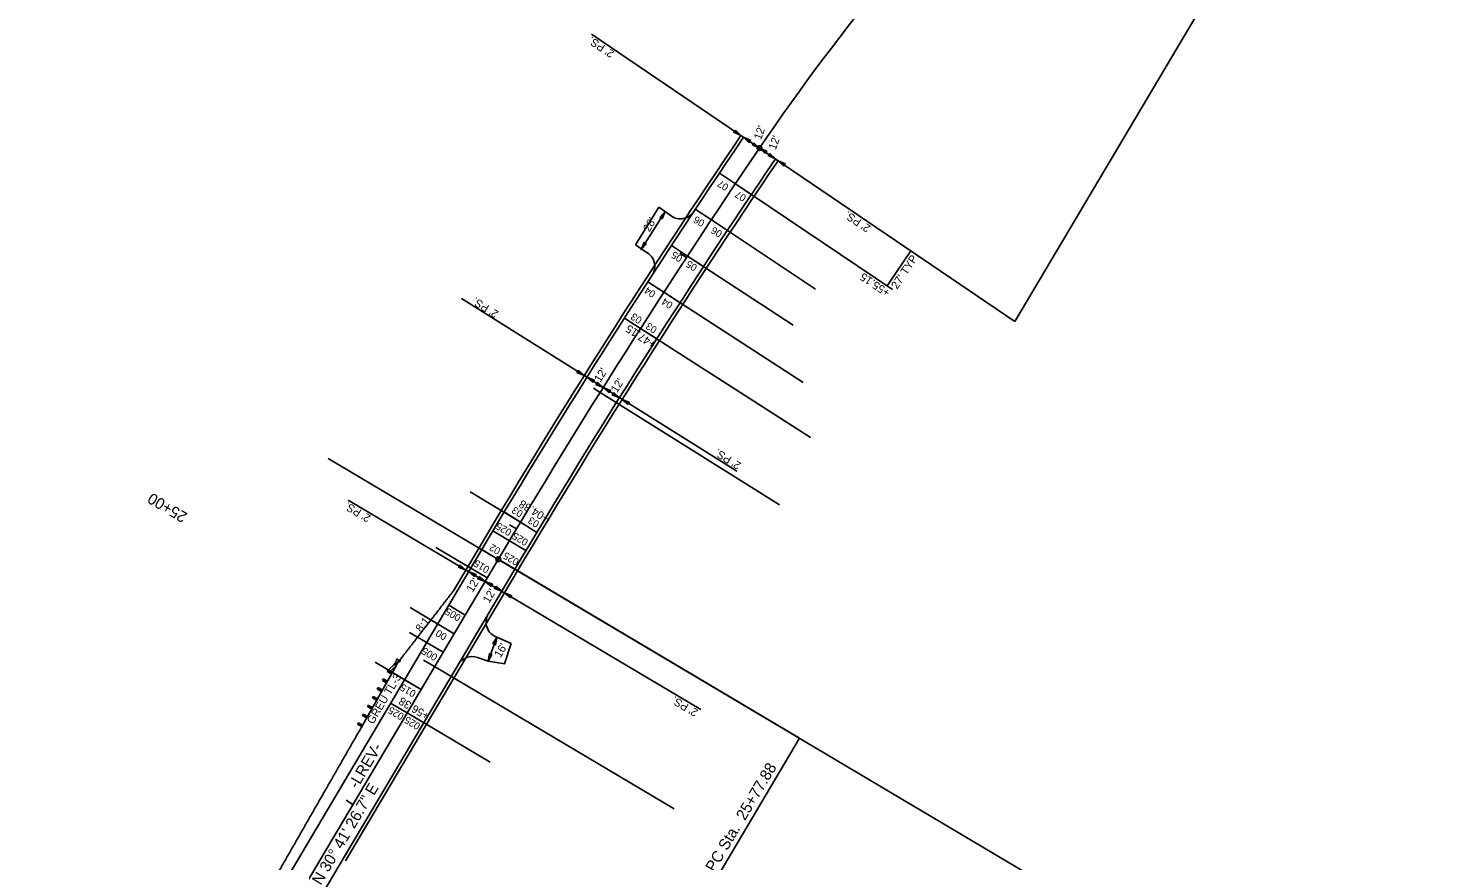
# Model space of a CAD drawing. Extents: x 2138032 to 2141863, y 405316 to 411953.
# Drawn here: x 2140967 to 2141846, y 410524 to 411044 of the extents above; entities that cross this region are included whole.
import ezdxf

# ---------------------------------------------------------------- set-up
doc = ezdxf.new("R2010")
doc.units = 0
for name, color, linetype in [('Prop Dimension', 7, 'Continuous'), ('Prop Dimension Text', 7, 'Continuous'), ('Prop EOT', 7, 'Continuous'), ('Prop Guardrail', 7, 'Continuous'), ('Prop Guardrail Anchor Unit CELL', 7, 'Continuous'), ('Prop Horizontal Alignment', 7, 'Continuous'), ('Prop Horizontal Alignment Direction Label', 7, 'Continuous'), ('Prop Horizontal Alignment Station Label', 7, 'Continuous'), ('Prop Horizontal Alignment Tick Label', 7, 'Continuous'), ('Prop Horizontal Alignment Tick Large', 7, 'Continuous'), ('Prop Horizontal Alignment Tick Small', 7, 'Continuous'), ('Prop Paved Shoulder', 7, 'Continuous'), ('Prop Superelevation  Arrow CELL', 7, 'Continuous'), ('Prop Superelevation Label', 7, 'Continuous'), ('Prop Terminator CELL', 7, 'Continuous'), ('Scratch_Level_5', 7, 'Continuous'), ('Scratch_Level_6', 7, 'Continuous'), ('Scratch_Level_7', 7, 'Continuous')]:
    doc.layers.add(name, color=color, linetype=linetype)

msp = doc.modelspace()

# ---------------------------------------------------------------- linework, layer by layer
at = {"layer": 'Prop Dimension'}
for p, q in [((2141583.48, 410860.49), (2141845.93, 411302.66)), ((2141319.23, 411039.91), (2141583.48, 410860.49)), ((2141507.25, 410880.38), (2141408.99, 410946.33)), ((2141350.17, 410905.39), (2141365.1, 410929.09)), ((2141503.78, 410882.7), (2141518.6, 410904.54)), ((2141409.88, 410766.94), (2141238.04, 410874.86)), ((2141259.95, 410663.36), (2141254.61, 410648.28))]:
    msp.add_line(p, q, dxfattribs=at)
at = {"layer": 'Prop Dimension Text'}
msp.add_line((2141167.11, 410748.94), (2141387.51, 410618.13), dxfattribs=at)
at = {"layer": 'Prop EOT'}
for p, q in [((2141361.18, 410931.91), (2141346.54, 410908.24)), ((2141361.18, 410931.91), (2141368.84, 410926.4)), ((2141346.54, 410908.24), (2141353.27, 410903.78)), ((2140946.62, 410205.9), (2141250.61, 410718.06)), ((2140967.26, 410193.65), (2141271.25, 410705.81)), ((2141268.96, 410659.34), (2141259.95, 410663.36)), ((2141268.96, 410659.34), (2141264.82, 410646.71)), ((2141254.61, 410648.28), (2141247.88, 410650.66)), ((2141264.95, 410646.71), (2141254.61, 410648.28))]:
    msp.add_line(p, q, dxfattribs=at)
for centre, radius, start, end in [((2145560.6, 408159.91), 5012, 145.82249, 149.30926), ((2145560.6, 408159.91), 4988, 145.82249, 149.30926), ((2141374.67, 410934.53), 10, 234.32649, 326.46189), ((2141348.68, 410894.9), 10, 327.00256, 62.64012), ((2141263.28, 410672.79), 10, 149.30926, 250.52331), ((2141244.55, 410641.23), 10, 70.52331, 149.30926)]:
    msp.add_arc(centre, radius, start, end, dxfattribs=at)
at = {"layer": 'Prop Guardrail'}
for points in [[(2141174.38, 410605.3), (2141173.6, 410603.94), (2141173.21, 410603.26), (2141172.83, 410602.58), (2141172.44, 410601.91), (2141172.05, 410601.23), (2141171.66, 410600.55), (2141171.27, 410599.87), (2141170.88, 410599.2), (2141170.49, 410598.52), (2141170.11, 410597.84), (2141169.72, 410597.16), (2141169.33, 410596.48), (2141168.94, 410595.81), (2141168.55, 410595.13), (2141168.16, 410594.45), (2141167.77, 410593.77), (2141167.39, 410593.09), (2141167, 410592.42), (2141166.61, 410591.74), (2141166.22, 410591.06), (2141165.83, 410590.38), (2141165.44, 410589.71), (2141165.05, 410589.03), (2141164.66, 410588.35), (2141164.28, 410587.67), (2141163.89, 410586.99), (2141163.5, 410586.32), (2141163.11, 410585.64), (2141162.72, 410584.96), (2141162.33, 410584.28), (2141161.94, 410583.6), (2141161.56, 410582.93), (2141161.17, 410582.25), (2141160.78, 410581.57), (2141160.39, 410580.89), (2141160, 410580.22), (2141159.61, 410579.54), (2141159.22, 410578.86), (2141158.84, 410578.18), (2141158.45, 410577.5), (2141158.06, 410576.83), (2141157.67, 410576.15), (2141157.28, 410575.47), (2141156.89, 410574.79), (2141156.5, 410574.11), (2141156.12, 410573.44), (2141155.73, 410572.76), (2141155.34, 410572.08), (2141154.95, 410571.4), (2141154.56, 410570.73), (2141154.17, 410570.05), (2141153.78, 410569.37), (2141153.4, 410568.69), (2141153.01, 410568.01), (2141152.62, 410567.34), (2141152.23, 410566.66), (2141151.84, 410565.98), (2141151.45, 410565.3), (2141151.06, 410564.62), (2141150.68, 410563.95), (2141150.29, 410563.27), (2141149.9, 410562.59), (2141149.51, 410561.91), (2141149.12, 410561.24), (2141148.73, 410560.56), (2141148.34, 410559.88), (2141147.96, 410559.2), (2141147.57, 410558.52), (2141147.18, 410557.85), (2141146.79, 410557.17), (2141146.4, 410556.49), (2141146.01, 410555.81), (2141145.62, 410555.13)], [(2141145.62, 410555.13), (2141145.24, 410554.46), (2141144.85, 410553.78), (2141144.46, 410553.1), (2141144.07, 410552.42), (2141143.68, 410551.75), (2141143.29, 410551.07), (2141142.9, 410550.39), (2141142.52, 410549.71), (2141142.13, 410549.03), (2141141.74, 410548.36), (2141141.35, 410547.68), (2141140.96, 410547), (2141140.57, 410546.32), (2141140.18, 410545.64), (2141139.8, 410544.97), (2141139.41, 410544.29), (2141139.02, 410543.61), (2141138.63, 410542.93), (2141138.24, 410542.26), (2141137.85, 410541.58), (2141137.46, 410540.9), (2141137.08, 410540.22), (2141136.69, 410539.54), (2141136.3, 410538.87), (2141135.91, 410538.19), (2141135.52, 410537.51), (2141135.13, 410536.83), (2141134.74, 410536.15), (2141134.36, 410535.48), (2141133.97, 410534.8), (2141133.58, 410534.12), (2141133.19, 410533.44), (2141132.8, 410532.77), (2141132.41, 410532.09), (2141132.02, 410531.41), (2141131.64, 410530.73), (2141131.25, 410530.05), (2141130.86, 410529.38), (2141130.47, 410528.7), (2141130.08, 410528.02), (2141129.69, 410527.34), (2141129.3, 410526.66), (2141128.92, 410525.99), (2141128.53, 410525.31), (2141128.14, 410524.63), (2141127.75, 410523.95), (2141127.36, 410523.28), (2141126.97, 410522.6), (2141126.58, 410521.92), (2141126.2, 410521.24), (2141125.81, 410520.56), (2141125.42, 410519.89), (2141125.03, 410519.21), (2141124.64, 410518.53), (2141124.25, 410517.85), (2141123.86, 410517.17), (2141123.47, 410516.5), (2141123.09, 410515.82), (2141122.7, 410515.14), (2141122.31, 410514.46), (2141121.92, 410513.79), (2141121.53, 410513.11), (2141121.14, 410512.43), (2141120.75, 410511.75), (2141120.37, 410511.07), (2141119.98, 410510.4), (2141119.59, 410509.72), (2141119.2, 410509.04), (2141118.81, 410508.36), (2141118.42, 410507.68), (2141118.03, 410507.01), (2141117.65, 410506.33), (2141117.26, 410505.65), (2141116.87, 410504.97)]]:
    msp.add_spline(points, degree=3, dxfattribs=at)
at = {"layer": 'Prop Guardrail Anchor Unit CELL'}
for p, q in [((2141174.38, 410605.3), (2141197.44, 410645.96)), ((2141192.11, 410642.78), (2141195.89, 410646.27)), ((2141193.45, 410642.02), (2141197.2, 410645.53)), ((2141195.89, 410646.27), (2141196.39, 410647.14)), ((2141195.89, 410646.27), (2141196.14, 410646.7)), ((2141197.69, 410646.4), (2141195.89, 410646.27)), ((2141197.2, 410645.53), (2141195.89, 410646.27)), ((2141197.38, 410648.41), (2141196.34, 410646.65)), ((2141196.34, 410646.65), (2141196.87, 410646.34)), ((2141197.69, 410646.4), (2141196.39, 410647.14)), ((2141196.39, 410647.14), (2141197.2, 410645.53)), ((2141196.87, 410646.34), (2141197.39, 410646.03)), ((2141199.78, 410648.36), (2141197.25, 410649.86)), ((2141197.25, 410649.86), (2141197.38, 410648.41)), ((2141197.39, 410646.03), (2141198.44, 410647.79)), ((2141198.44, 410647.79), (2141199.78, 410648.36)), ((2141188.57, 410636.39), (2141189.06, 410637.26)), ((2141190.37, 410636.52), (2141188.57, 410636.39)), ((2141191.18, 410634.91), (2141188.57, 410636.39)), ((2141191.67, 410635.78), (2141189.06, 410637.26)), ((2141189.06, 410637.26), (2141189.87, 410635.65)), ((2141189.87, 410635.65), (2141190.37, 410636.52)), ((2141189.87, 410635.65), (2141191.67, 410635.78)), ((2141191.18, 410634.91), (2141190.37, 410636.52)), ((2141191.62, 410641.91), (2141192.11, 410642.78)), ((2141193.45, 410642.02), (2141191.62, 410641.91)), ((2141194.29, 410640.39), (2141191.62, 410641.91)), ((2141194.78, 410641.26), (2141192.11, 410642.78)), ((2141192.11, 410642.78), (2141192.95, 410641.15)), ((2141192.95, 410641.15), (2141193.45, 410642.02)), ((2141192.95, 410641.15), (2141194.78, 410641.26)), ((2141194.29, 410640.39), (2141193.45, 410642.02)), ((2141182.32, 410625.45), (2141182.81, 410626.32)), ((2141185.45, 410624.82), (2141182.81, 410626.32)), ((2141182.81, 410626.32), (2141183.64, 410624.7)), ((2141185.34, 410630.98), (2141185.83, 410631.85)), ((2141187.2, 410631.08), (2141185.34, 410630.98)), ((2141188.07, 410629.43), (2141185.34, 410630.98)), ((2141188.56, 410630.3), (2141185.83, 410631.85)), ((2141185.83, 410631.85), (2141186.7, 410630.21)), ((2141186.7, 410630.21), (2141187.2, 410631.08)), ((2141186.7, 410630.21), (2141188.56, 410630.3)), ((2141188.07, 410629.43), (2141187.2, 410631.08)), ((2141179.2, 410619.97), (2141179.69, 410620.84)), ((2141181.02, 410620.09), (2141179.2, 410619.97)), ((2141181.85, 410618.47), (2141179.2, 410619.97)), ((2141182.34, 410619.34), (2141179.69, 410620.84)), ((2141179.69, 410620.84), (2141180.53, 410619.22)), ((2141180.53, 410619.22), (2141181.02, 410620.09)), ((2141180.53, 410619.22), (2141182.34, 410619.34)), ((2141181.85, 410618.47), (2141181.02, 410620.09)), ((2141184.13, 410625.57), (2141182.32, 410625.45)), ((2141184.96, 410623.95), (2141182.32, 410625.45)), ((2141183.64, 410624.7), (2141184.13, 410625.57)), ((2141183.64, 410624.7), (2141185.45, 410624.82)), ((2141184.96, 410623.95), (2141184.13, 410625.57)), ((2141184.96, 410623.95), (2141185.45, 410624.82)), ((2141173.02, 410608.99), (2141173.52, 410609.86)), ((2141174.82, 410609.12), (2141173.02, 410608.99)), ((2141175.63, 410607.51), (2141173.02, 410608.99)), ((2141176.13, 410608.38), (2141173.52, 410609.86)), ((2141173.52, 410609.86), (2141174.33, 410608.25)), ((2141174.33, 410608.25), (2141174.82, 410609.12)), ((2141176.13, 410608.38), (2141174.82, 410609.12)), ((2141174.82, 410609.12), (2141175.63, 410607.51)), ((2141176.09, 410614.49), (2141176.58, 410615.36)), ((2141177.91, 410614.61), (2141176.09, 410614.49)), ((2141178.74, 410612.99), (2141176.09, 410614.49)), ((2141179.24, 410613.86), (2141176.58, 410615.36)), ((2141176.58, 410615.36), (2141177.42, 410613.74)), ((2141177.42, 410613.74), (2141177.91, 410614.61)), ((2141177.42, 410613.74), (2141179.24, 410613.86)), ((2141178.74, 410612.99), (2141177.91, 410614.61)), ((2141174.33, 410608.25), (2141176.13, 410608.38)), ((2141175.63, 410607.51), (2141176.13, 410608.38))]:
    msp.add_line(p, q, dxfattribs=at)
at = {"layer": 'Prop Horizontal Alignment'}
msp.add_line((2140956.94, 410199.77), (2141260.93, 410711.93), dxfattribs=at)
for centre, radius, start, end in [((2142623.69, 410154.16), 1450, 135.01552, 145.82249), ((2145560.6, 408159.91), 5000, 145.82249, 149.30926)]:
    msp.add_arc(centre, radius, start, end, dxfattribs=at)
at = {"layer": 'Prop Horizontal Alignment Station Label'}
for p in [(2141262.22, 410711.17), (2141381.04, 410485.62)]:
    msp.add_line(p, (2141449.08, 410600.26), dxfattribs=at)
for centre in [(2141424.1, 410968.71), (2141260.93, 410711.93)]:
    msp.add_circle(centre, 1.5, dxfattribs=at)
at = {"layer": 'Prop Horizontal Alignment Tick Large'}
msp.add_line((2141221.18, 410644.96), (2141214.3, 410649.05), dxfattribs=at)
at = {"layer": 'Prop Horizontal Alignment Tick Small'}
for p, q in [((2141378.51, 410900.36), (2141374.33, 410903.1)), ((2141324.54, 410816.18), (2141320.3, 410818.84)), ((2141272.26, 410730.93), (2141267.98, 410733.5)), ((2141170.14, 410558.97), (2141165.84, 410561.52))]:
    msp.add_line(p, q, dxfattribs=at)
at = {"layer": 'Prop Paved Shoulder'}
for p, q in [((2141424.1, 410968.71), (2141412.52, 410976.57)), ((2141435.68, 410960.84), (2141424.1, 410968.71)), ((2141233.04, 410692.37), (2141248.89, 410719.08)), ((2141165.48, 410523.69), (2141272.97, 410704.79))]:
    msp.add_line(p, q, dxfattribs=at)
for radius in [5014, 4986]:
    msp.add_arc((2145560.6, 408159.91), radius, 145.82249, 149.30926, dxfattribs=at)
msp.add_spline([(2141198.44, 410647.79), (2141198.9, 410648.39), (2141199.37, 410648.99), (2141199.84, 410649.6), (2141200.31, 410650.2), (2141200.77, 410650.8), (2141201.24, 410651.4), (2141201.71, 410652.01), (2141202.18, 410652.61), (2141202.65, 410653.21), (2141203.11, 410653.81), (2141203.58, 410654.42), (2141204.05, 410655.02), (2141204.52, 410655.62), (2141204.98, 410656.22), (2141205.45, 410656.83), (2141205.92, 410657.43), (2141206.39, 410658.03), (2141206.85, 410658.63), (2141207.32, 410659.24), (2141207.79, 410659.84), (2141208.26, 410660.44), (2141208.72, 410661.04), (2141209.19, 410661.65), (2141209.66, 410662.25), (2141210.13, 410662.85), (2141210.59, 410663.45), (2141211.06, 410664.06), (2141211.53, 410664.66), (2141212, 410665.26), (2141212.46, 410665.86), (2141212.93, 410666.47), (2141213.4, 410667.07), (2141213.87, 410667.67), (2141214.34, 410668.27), (2141214.8, 410668.88), (2141215.27, 410669.48), (2141215.74, 410670.08), (2141216.21, 410670.68), (2141216.67, 410671.29), (2141217.14, 410671.89), (2141217.61, 410672.49), (2141218.08, 410673.09), (2141218.54, 410673.7), (2141219.01, 410674.3), (2141219.48, 410674.9), (2141219.95, 410675.5), (2141220.41, 410676.11), (2141220.88, 410676.71), (2141221.35, 410677.31), (2141221.82, 410677.91), (2141222.28, 410678.52), (2141222.75, 410679.12), (2141223.22, 410679.72), (2141223.69, 410680.32), (2141224.16, 410680.93), (2141224.62, 410681.53), (2141225.09, 410682.13), (2141225.56, 410682.73), (2141226.03, 410683.34), (2141226.49, 410683.94), (2141226.96, 410684.54), (2141227.43, 410685.14), (2141227.9, 410685.75), (2141228.36, 410686.35), (2141228.83, 410686.95), (2141229.3, 410687.55), (2141229.77, 410688.16), (2141230.23, 410688.76), (2141230.7, 410689.36), (2141231.17, 410689.96), (2141231.64, 410690.56), (2141232.1, 410691.17), (2141233.04, 410692.37)], degree=3, dxfattribs=at)
at = {"layer": 'Prop Superelevation  Arrow CELL'}
for p, q in [((2141399.02, 410953.01), (2141408.99, 410946.33)), ((2141408.99, 410946.33), (2141418.95, 410939.64)), ((2141384, 410930.5), (2141394, 410923.87)), ((2141394, 410923.87), (2141404, 410917.23)), ((2141369.1, 410907.91), (2141379.14, 410901.33)), ((2141379.14, 410901.33), (2141389.17, 410894.75)), ((2141354.32, 410885.23), (2141364.4, 410878.71)), ((2141364.4, 410878.71), (2141374.47, 410872.18)), ((2141339.67, 410862.48), (2141349.78, 410856.01)), ((2141349.78, 410856.01), (2141359.88, 410849.54)), ((2141264.64, 410741.57), (2141274.78, 410735.14)), ((2141274.78, 410735.14), (2141284.91, 410728.72)), ((2141257.54, 410729.69), (2141267.84, 410723.54)), ((2141267.84, 410723.54), (2141278.14, 410717.38)), ((2141250.61, 410718.06), (2141260.93, 410711.93)), ((2141243.72, 410706.45), (2141254.04, 410700.33)), ((2141260.93, 410711.93), (2141271.25, 410705.81)), ((2141229.94, 410683.23), (2141240.26, 410677.11)), ((2141223.05, 410671.62), (2141233.37, 410665.5)), ((2141233.37, 410665.5), (2141223.05, 410671.62)), ((2141226.48, 410653.89), (2141216.16, 410660.02)), ((2141212.7, 410630.67), (2141202.38, 410636.8)), ((2141204.02, 410616.05), (2141193.7, 410622.18)), ((2141204.02, 410616.05), (2141214.34, 410609.93))]:
    msp.add_line(p, q, dxfattribs=at)
at = {"layer": 'Prop Terminator CELL'}
for points in [[(2141409, 410979.96), (2141412.52, 410976.57), (2141408.03, 410978.58), (2141409.02, 410978.94)], [(2141417.68, 410972.06), (2141414.17, 410975.45), (2141418.65, 410973.44), (2141417.66, 410973.08)], [(2141420.58, 410972.09), (2141424.1, 410968.71), (2141419.62, 410970.72), (2141420.61, 410971.08)], [(2141427.61, 410965.32), (2141424.1, 410968.71), (2141428.58, 410966.7), (2141427.59, 410966.34)], [(2141430.51, 410965.35), (2141434.03, 410961.97), (2141429.54, 410963.98), (2141430.53, 410964.34)], [(2141439.19, 410957.46), (2141435.68, 410960.84), (2141440.16, 410958.83), (2141439.17, 410958.47)], [(2141361.84, 410925.46), (2141365.1, 410929.09), (2141363.25, 410924.54), (2141362.85, 410925.52)], [(2141353.44, 410909.02), (2141350.17, 410905.39), (2141352.03, 410909.94), (2141352.42, 410908.96)], [(2141310.99, 410829.97), (2141314.62, 410826.71), (2141310.07, 410828.56), (2141311.05, 410828.96)], [(2141319.94, 410822.39), (2141316.31, 410825.65), (2141320.86, 410823.8), (2141319.89, 410823.4)], [(2141322.84, 410822.52), (2141326.47, 410819.26), (2141321.92, 410821.11), (2141322.9, 410821.51)], [(2141330.1, 410816), (2141326.47, 410819.26), (2141331.02, 410817.41), (2141330.05, 410817.01)], [(2141333, 410816.13), (2141336.63, 410812.87), (2141332.08, 410814.72), (2141333.06, 410815.12)], [(2141341.95, 410808.55), (2141338.32, 410811.81), (2141342.87, 410809.96), (2141341.9, 410809.56)], [(2141236.98, 410708.44), (2141240.69, 410705.27), (2141236.1, 410707), (2141237.06, 410707.42)], [(2141246.13, 410701.08), (2141242.41, 410704.25), (2141247.01, 410702.51), (2141246.04, 410702.09)], [(2141249.02, 410701.29), (2141252.73, 410698.12), (2141248.14, 410699.86), (2141249.1, 410700.28)], [(2141256.45, 410694.96), (2141252.73, 410698.12), (2141257.33, 410696.39), (2141256.36, 410695.97)], [(2141259.34, 410695.17), (2141263.05, 410692), (2141258.46, 410693.73), (2141259.42, 410694.15)], [(2141268.49, 410687.81), (2141264.77, 410690.98), (2141269.37, 410689.24), (2141268.4, 410688.82)], [(2141257.56, 410659.1), (2141259.95, 410663.36), (2141259.14, 410658.52), (2141258.54, 410659.38)], [(2141256.99, 410652.53), (2141254.61, 410648.28), (2141255.42, 410653.12), (2141256.02, 410652.26)]]:
    msp.add_lwpolyline(points, close=True, dxfattribs=at)
at = {"layer": 'Scratch_Level_5'}
for p, q in [((2141459.16, 410880.64), (2141394, 410923.87)), ((2141445.01, 410858.14), (2141379.14, 410901.33)), ((2141451.34, 410822.37), (2141364.4, 410878.71)), ((2141455.88, 410788.07), (2141349.78, 410856.01)), ((2141436.52, 410745.96), (2141324.54, 410816.18)), ((2141243.28, 410754.04), (2141274.78, 410735.12)), ((2141221.91, 410719.4), (2141254.04, 410700.33)), ((2141205.96, 410681.77), (2141233.37, 410665.5)), ((2141205.53, 410666.33), (2141226.48, 410653.89)), ((2141184.03, 410647.69), (2141212.7, 410630.67)), ((2141255.83, 410585.31), (2141204.02, 410616.05))]:
    msp.add_line(p, q, dxfattribs=at)
at = {"layer": 'Scratch_Level_6'}
msp.add_line((2141370.73, 410556.2), (2141221.18, 410644.96), dxfattribs=at)
at = {"layer": 'Scratch_Level_7'}
msp.add_line((2141662.3, 410473.71), (2141154.76, 410774.95), dxfattribs=at)

# ---------------------------------------------------------------- texts
at = {"layer": 'Prop Dimension'}
msp.add_text('+55.15', height=5, rotation=146.30414, dxfattribs=at).set_placement((2141506.18, 410879.68))
at = {"layer": 'Prop Dimension Text'}
for s, rotation, p in [("2' PS.", 146.41674, (2141333.86, 411028.84)), ("12'", 70.11623, (2141425.02, 410973.47)), ("12'", 70.11623, (2141434.18, 410967.2)), ("28'", 59.30926, (2141355.3, 410915.99)), ("2' PS.", 146.41674, (2141493.92, 410919.88)), ("27' TYP.", 56.42281, (2141510.07, 410880.24)), ("2' PS.", 147.83829, (2141261.54, 410866.44)), ('+47.15', 146.7084, (2141359.88, 410847.41)), ("12'", 57.83829, (2141324.64, 410822.08)), ("12'", 57.83829, (2141335.03, 410815.55)), ("2' PS.", 147.83829, (2141412.96, 410771.84)), ("2' PS.", 149.30926, (2141181.75, 410739.01)), ('+04.88', 149.30926, (2141293.47, 410738.78)), ("12'", 59.30926, (2141244.89, 410690.9)), ("12'", 59.30926, (2141255.18, 410684.17)), ('8:1', 52.1831, (2141212.66, 410666.11)), ("16'", 59.30926, (2141262.32, 410650.12)), ("2' PS.", 149.30926, (2141386.18, 410617.68)), ('+56.38', 149.30926, (2141218.45, 410615.66))]:
    msp.add_text(s, height=5, rotation=rotation, dxfattribs=at).set_placement(p)
at = {"layer": 'Prop Guardrail Anchor Unit CELL'}
msp.add_text('GREU TL-3', height=5, rotation=59.30926, dxfattribs=at).set_placement((2141182.77, 410608.6))
at = {"layer": 'Prop Horizontal Alignment Direction Label'}
for s, p in [('-LREV-', (2141172.92, 410568.28)), ('N 30%%d 41\' 26.7" E', (2141150.05, 410508.13))]:
    msp.add_text(s, height=7, rotation=59.30926, dxfattribs=at).set_placement(p)
at = {"layer": 'Prop Horizontal Alignment Station Label'}
msp.add_text('-LREV- PC Sta.  25+77.88', height=7, rotation=59.30926, dxfattribs=at).set_placement((2141378.88, 410487.61))
at = {"layer": 'Prop Horizontal Alignment Tick Label'}
msp.add_text('25+00', height=7, rotation=149.30926, dxfattribs=at).set_placement((2141067.26, 410740.39))
at = {"layer": 'Prop Superelevation Label'}
for s, rotation, p in [('07', 148.45804, (2141405.26, 410945.54)), ('07', 148.45804, (2141416.2, 410938.82)), ('06', 148.76743, (2141390.28, 410923.06)), ('06', 148.76743, (2141401.26, 410916.4)), ('05', 147.91368, (2141376.5, 410901.02)), ('05', 147.91368, (2141385.62, 410895.3)), ('04', 147.06014, (2141359.66, 410878.75)), ('04', 147.06014, (2141370.44, 410871.77)), ('03', 147.36953, (2141351.16, 410862.41)), ('03', 147.36953, (2141360.53, 410856.41)), ('03', 147.64302, (2141276.86, 410741.59)), ('025', 149.15453, (2141269.75, 410730.04)), ('03', 147.64302, (2141287, 410735.17)), ('025', 149.15453, (2141280.06, 410723.89)), ('02', 149.30926, (2141262.83, 410718.44)), ('025', 149.30926, (2141274.32, 410711.62)), ('015', 149.30926, (2141255.94, 410706.84)), ('005', 149.30926, (2141238.1, 410676.78)), ('00', 149.30926, (2141229.35, 410664.91)), ('005', 149.30926, (2141223.44, 410652.08)), ('015', 149.30926, (2141209.97, 410629.38)), ('025', 149.30926, (2141202.43, 410615.12)), ('025', 149.30926, (2141212.64, 410609.05))]:
    msp.add_text(s, height=4.5, rotation=rotation, dxfattribs=at).set_placement(p)

doc.saveas('drawing.dxf')
